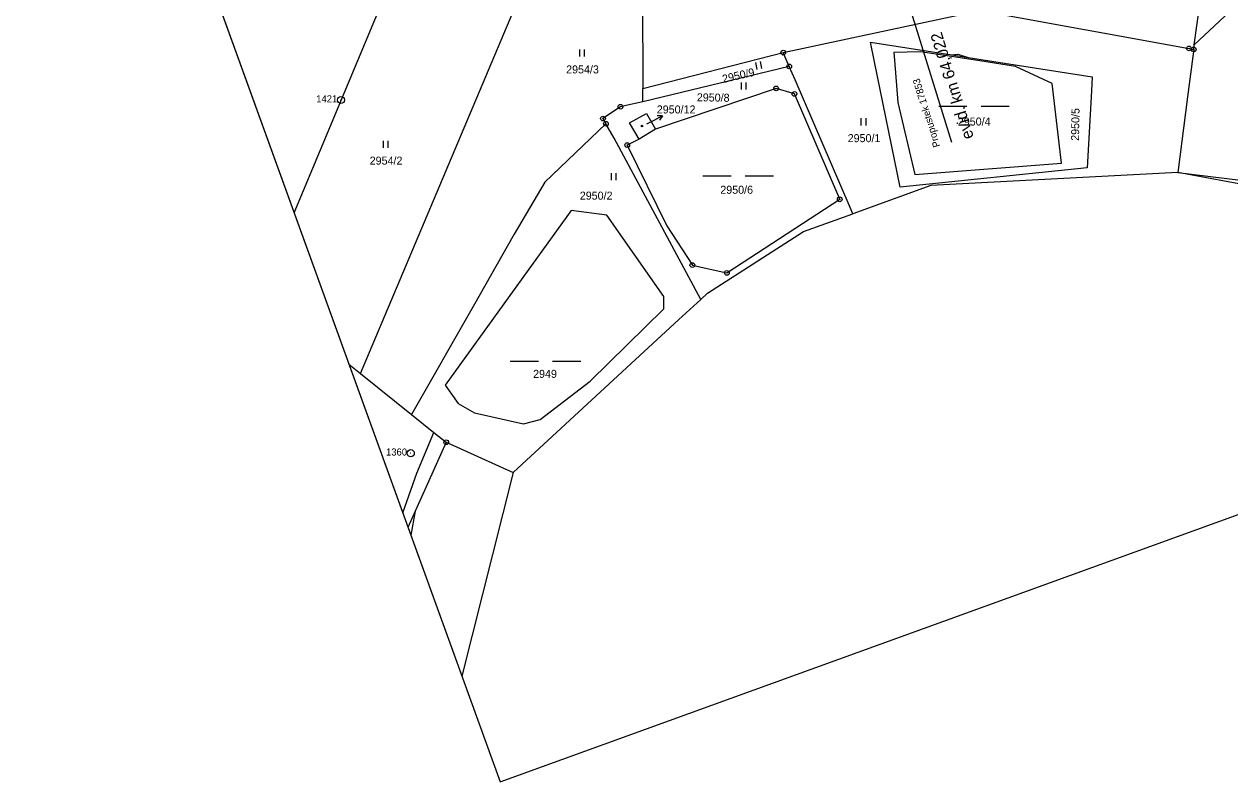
# Model space of a CAD drawing. Extents: x -620552 to -620056, y -1123312 to -1122890.
# Drawn here: x -620552.1 to -620295.9, y -1123311.9 to -1123150.9 of the extents above; entities that cross this region are included whole.
import ezdxf

# ---------------------------------------------------------------- set-up
doc = ezdxf.new("R2010")
doc.units = 0
for name, color, linetype in [('Hranice parcel', 7, 'Continuous'), ('Parcelní čísla', 7, 'Continuous'), ('Pop  PČ popisy', 7, 'Continuous'), ('Rámečky', 7, 'Continuous'), ('Rámečky-tisk', 7, 'Continuous'), ('Vnitřní kresba', 7, 'Continuous'), ('Vrstva 19', 7, 'Continuous'), ('Značky bodu BP', 7, 'Continuous'), ('Značky budov', 7, 'Continuous'), ('Značky kultur', 7, 'Continuous')]:
    doc.layers.add(name, color=color, linetype=linetype)

msp = doc.modelspace()

# ---------------------------------------------------------------- linework, layer by layer
at = {"layer": 'Hranice parcel'}
for p, q in [((-620303.5, -1123155.32), (-620298.49, -1123117.9)), ((-620420.8, -1123130.97), (-620420.66, -1123164.55)), ((-620480.65, -1123225.1), (-620442.33, -1123134.4)), ((-620494.75, -1123190.98), (-620473.69, -1123140.72)), ((-620303.63, -1123156.28), (-620303.5, -1123155.32)), ((-620420.66, -1123164.55), (-620390.82, -1123156.97)), ((-620389.56, -1123159.9), (-620390.82, -1123156.97)), ((-620389.56, -1123159.9), (-620420.67, -1123167.38)), ((-620420.67, -1123167.38), (-620420.66, -1123164.55)), ((-620304.97, -1123166.33), (-620307.01, -1123182.39)), ((-620417.95, -1123173.25), (-620421.43, -1123175.35)), ((-620307.01, -1123182.39), (-620259.01, -1123188.34)), ((-620259.81, -1123191.23), (-620307.01, -1123182.39)), ((-620483.1, -1123223.13), (-620480.65, -1123225.1)), ((-620483.1, -1123223.13), (-620480.65, -1123225.1)), ((-620480.65, -1123225.1), (-620469.81, -1123233.8)), ((-620480.65, -1123225.1), (-620469.81, -1123233.8)), ((-620469.81, -1123233.8), (-620465.05, -1123237.62)), ((-620469.81, -1123233.8), (-620465.05, -1123237.62)), ((-620465.05, -1123237.62), (-620462.42, -1123239.73)), ((-620465.05, -1123237.62), (-620462.42, -1123239.73)), ((-620462.42, -1123239.73), (-620448.18, -1123246.14)), ((-620448.18, -1123246.14), (-620459.12, -1123289.37)), ((-620469, -1123254.37), (-620470.55, -1123257.81)), ((-620469, -1123254.37), (-620470.55, -1123257.81))]:
    msp.add_line(p, q, dxfattribs=at)
for points in [[(-620267.31, -1123105.13), (-620271.09, -1123121.69), (-620283, -1123136.04), (-620303.5, -1123155.32)], [(-620390.82, -1123156.97), (-620349.09, -1123147.99), (-620304.63, -1123156.08), (-620303.63, -1123156.28)], [(-620372.3, -1123154.73), (-620354.98, -1123157.43), (-620353.71, -1123157.32)], [(-620353.71, -1123157.32), (-620351.54, -1123157.97), (-620325.21, -1123162.08), (-620325.37, -1123165.05), (-620326.24, -1123181.42), (-620366.02, -1123185.52), (-620371.44, -1123158.94), (-620372.3, -1123154.73)], [(-620366.46, -1123167.58), (-620362.9, -1123182.84), (-620331.75, -1123180.43), (-620333.71, -1123163.55), (-620341.51, -1123159.88), (-620349.04, -1123158.72), (-620356.47, -1123157.57), (-620361.65, -1123156.77), (-620367.33, -1123156.94), (-620367.2, -1123158.55), (-620366.46, -1123167.58)], [(-620303.63, -1123156.28), (-620303.83, -1123157.77), (-620304.97, -1123166.33)], [(-620376.06, -1123191.18), (-620376.64, -1123189.84), (-620388.32, -1123162.77), (-620389.56, -1123159.9)], [(-620421.43, -1123175.35), (-620423.97, -1123176.6), (-620415.57, -1123193.78), (-620410.14, -1123202.09), (-620408.92, -1123202.36), (-620402.8, -1123203.74), (-620378.83, -1123188.12), (-620388.45, -1123165.73), (-620392.34, -1123164.57), (-620417.95, -1123173.25)], [(-620420.67, -1123167.38), (-620424.53, -1123168.26), (-620425.41, -1123168.46), (-620429.12, -1123170.97), (-620428.51, -1123172.06)], [(-620421.43, -1123175.35), (-620423.5, -1123171.89), (-620419.89, -1123169.88), (-620417.95, -1123173.25)], [(-620428.51, -1123172.06), (-620441.5, -1123184.51), (-620447.97, -1123195.52), (-620456.72, -1123210.85), (-620469.81, -1123233.8)], [(-620408.37, -1123209.4), (-620426.77, -1123175.15), (-620428.51, -1123172.06)], [(-620307.01, -1123182.39), (-620359.5, -1123185.17), (-620376.06, -1123191.18)], [(-620459.9, -1123231.5), (-620456.4, -1123233.47), (-620446.03, -1123235.78), (-620442.49, -1123234.88), (-620431.86, -1123226.73), (-620416.2, -1123211.37), (-620416.17, -1123208.77), (-620428.32, -1123191.51), (-620435.86, -1123190.48), (-620462.66, -1123227.61), (-620459.9, -1123231.5)], [(-620408.37, -1123209.4), (-620406.9, -1123208.04), (-620386.54, -1123194.99), (-620376.06, -1123191.18)], [(-620448.18, -1123246.14), (-620413, -1123213.67), (-620408.37, -1123209.4)], [(-620471.67, -1123254.71), (-620468.69, -1123246.27), (-620465.05, -1123237.62)], [(-620462.42, -1123239.73), (-620467.02, -1123249.97), (-620469, -1123254.37)], [(-620462.42, -1123239.73), (-620467.02, -1123249.97), (-620469, -1123254.37)], [(-620469, -1123254.37), (-620469.96, -1123259.44)]]:
    msp.add_lwpolyline(points, dxfattribs=at)
at = {"layer": 'Pop  PČ popisy'}
for p, q in [((-620419.13, -1123171.75), (-620416.46, -1123170.39)), ((-620416.46, -1123170.39), (-620417.58, -1123170.4)), ((-620416.46, -1123170.39), (-620417.12, -1123171.29)), ((-620419.81, -1123172.09), (-620419.13, -1123171.75))]:
    msp.add_line(p, q, dxfattribs=at)
at = {"layer": 'Rámečky'}
msp.add_lwpolyline([(-620552.1, -1123032.6), (-620450.98, -1123311.85), (-620056.07, -1123168.86)], dxfattribs=at)
at = {"layer": 'Rámečky-tisk'}
msp.add_line((-620552.1, -1123032.6), (-620450.98, -1123311.85), dxfattribs=at)
msp.add_lwpolyline([(-620450.98, -1123311.85), (-620056.07, -1123168.86), (-620157.19, -1122889.6), (-620552.1, -1123032.6)], dxfattribs=at)
at = {"layer": 'Vnitřní kresba'}
msp.add_line((-620354.98, -1123157.43), (-620351.54, -1123157.97), dxfattribs=at)
at = {"layer": 'Vrstva 19'}
msp.add_line((-620355.01, -1123176.04), (-620372.81, -1123118.74), dxfattribs=at)
at = {"layer": 'Značky bodu BP'}
for centre, radius in [((-620304.63, -1123156.08), 0.5), ((-620390.82, -1123156.97), 0.5), ((-620390.82, -1123156.97), 0.0303), ((-620304.63, -1123156.08), 0.0303), ((-620303.63, -1123156.28), 0.5), ((-620303.63, -1123156.28), 0.0303), ((-620389.56, -1123159.9), 0.5), ((-620389.56, -1123159.9), 0.0303), ((-620392.34, -1123164.57), 0.5), ((-620392.34, -1123164.57), 0.0303), ((-620388.45, -1123165.73), 0.5), ((-620388.45, -1123165.73), 0.0303), ((-620484.79, -1123167.02), 0.75), ((-620484.79, -1123167.02), 0.03), ((-620425.41, -1123168.46), 0.5), ((-620425.41, -1123168.46), 0.0303), ((-620429.12, -1123170.97), 0.5), ((-620429.12, -1123170.97), 0.0303), ((-620428.51, -1123172.06), 0.5), ((-620428.51, -1123172.06), 0.0303), ((-620423.97, -1123176.6), 0.5), ((-620423.97, -1123176.6), 0.0303), ((-620378.83, -1123188.12), 0.5), ((-620378.83, -1123188.12), 0.0303), ((-620410.14, -1123202.09), 0.5), ((-620410.14, -1123202.09), 0.0303), ((-620402.8, -1123203.74), 0.5), ((-620402.8, -1123203.74), 0.0303), ((-620462.42, -1123239.73), 0.5), ((-620462.42, -1123239.73), 0.0303), ((-620469.96, -1123242.04), 0.75), ((-620469.96, -1123242.04), 0.03)]:
    msp.add_circle(centre, radius, dxfattribs=at)
at = {"layer": 'Značky budov'}
msp.add_circle((-620420.82, -1123172.55), 0.175, dxfattribs=at)
at = {"layer": 'Značky kultur'}
for p, q in [((-620434.06, -1123157.81), (-620434.06, -1123156.31)), ((-620433.06, -1123157.81), (-620433.06, -1123156.31)), ((-620396.39, -1123160.52), (-620396.62, -1123159.04)), ((-620395.4, -1123160.36), (-620395.63, -1123158.88)), ((-620399.71, -1123164.81), (-620399.71, -1123163.31)), ((-620398.71, -1123164.81), (-620398.71, -1123163.31)), ((-620357.8, -1123168.35), (-620351.8, -1123168.35)), ((-620348.8, -1123168.35), (-620342.8, -1123168.35)), ((-620374.24, -1123172.41), (-620374.24, -1123170.91)), ((-620373.24, -1123172.41), (-620373.24, -1123170.91)), ((-620475.78, -1123177.18), (-620475.78, -1123175.68)), ((-620474.78, -1123177.18), (-620474.78, -1123175.68)), ((-620427.33, -1123184.04), (-620427.33, -1123182.54)), ((-620426.33, -1123184.04), (-620426.33, -1123182.54)), ((-620407.9, -1123183.15), (-620401.9, -1123183.15)), ((-620398.9, -1123183.15), (-620392.9, -1123183.15)), ((-620448.85, -1123222.47), (-620442.85, -1123222.47)), ((-620439.85, -1123222.47), (-620433.85, -1123222.47))]:
    msp.add_line(p, q, dxfattribs=at)

# ---------------------------------------------------------------- texts
at = {"layer": 'Parcelní čísla'}
for s, p in [('2954/3', (-620436.95, -1123161.38)), ('2950/12', (-620417.69, -1123169.88)), ('2950/4', (-620353.74, -1123172.45)), ('2950/1', (-620377.14, -1123175.98)), ('2954/2', (-620478.68, -1123180.75)), ('2950/2', (-620434.05, -1123188.19)), ('2950/6', (-620404.2, -1123186.94)), ('2949', (-620443.97, -1123226.04))]:
    msp.add_text(s, height=1.7, dxfattribs=at).set_placement(p)
for s, rotation, p in [('2950/9', 13, (-620403.57, -1123163.42)), ('2950/8', 359, (-620409.2, -1123167.29)), ('2950/5', 89, (-620328, -1123175.71))]:
    msp.add_text(s, height=1.7, rotation=rotation, dxfattribs=at).set_placement(p)
at = {"layer": 'Vrstva 19'}
for s, height, p in [('evid. km 64,022', 2.5, (-620350.32, -1123174.96)), ('Propustek 17853', 1.5, (-620357.48, -1123176.82))]:
    msp.add_text(s, height=height, rotation=107.0012, dxfattribs=at).set_placement(p)
at = {"layer": 'Značky bodu BP'}
for s, p in [('1421', (-620490.04, -1123167.52)), ('1360', (-620475.21, -1123242.54))]:
    msp.add_text(s, height=1.5, dxfattribs=at).set_placement(p)

doc.saveas('drawing.dxf')
